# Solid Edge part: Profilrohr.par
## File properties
Username: ahadarics
Dokumentum tartalom típus: 0
Author: ahadarics
Last saved by: ahadarics
Revision: 83
Sűrűség: 0,000 kg/m^3
Pontosság: 0,990
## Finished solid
Body 1: solid body, 6 faces, 6 edges, 0 vertices.
  Faces by surface: cone 2, cylinder 2, plane 2
  Edges by curve: circle 6
Bounding box of the edges (mm): 21.270 x 21.270 x 232.000, from (-10.635, -10.635, -211) to (10.635, 10.635, 21).
Cylindrical faces by radius (mm): R10 x1, R10.635 x1
Conical faces (half-angle, radius in mm at the cone's reference point): 15 deg R10.067 x2
Planar faces by outward normal: +z 1, -z 1
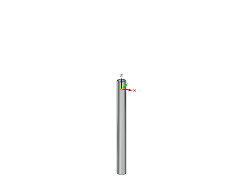
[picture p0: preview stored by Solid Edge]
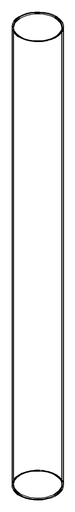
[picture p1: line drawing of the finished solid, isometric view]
